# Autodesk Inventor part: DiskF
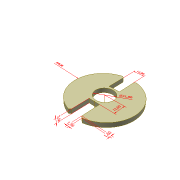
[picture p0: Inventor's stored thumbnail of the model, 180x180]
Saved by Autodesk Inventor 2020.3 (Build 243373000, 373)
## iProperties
Created: 2013-08
Part Number: DiskF
Document SubType Name: Modeling
Designer: hunter love
Density: 1 g/cm^3
Mass: 14.7916 g
Surface Area: 77.5573 cm^2
Volume: 14.7916 cm^3
Material: Generico
Appearance: Nylon 6
Author: hunter love
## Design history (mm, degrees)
node "Annotazioni"
  node "Quota radiale 1" dims "d20" = 35 (derived), "d22" = 21 (derived)
  node "Quota diametro 1" dims "d22" = 21 (derived)
  node "Quota lineare 1" dims "d22" = 21 (derived), "d25" = 12 (derived)
  node "Quota lineare 2" dims "d22" = 21 (derived), "d28" = 5 (derived)
  node "Quota lineare 3" dims "d22" = 21 (derived), "d29" = 1.95741 (derived)
  node "Quota lineare 4" dims "d22" = 21 (derived), "d30" = 1.60154 (derived)
  node "Quota lineare 5" dims "d22" = 21 (derived), "d33" = 12.5 (derived)
sketch "Sketch1"
  geometry: L1 (-6, -34.482)-(-6, -12.5); L2 (-6, -12.5)-(6, -12.5); L3 (6, -12.5)-(6, -34.482); L4 (6, 34.482)-(6, 12.5); L5 (6, 12.5)-(-6, 12.5); L6 (-6, 12.5)-(-6, 34.482); L7 (0, 0)-(30.757, 0) reference; L8 (0, 0)-(0, 25.868) reference; A1 r 35 centre (0, 0) between (-6, 34.482) and (-6, -34.482); A2 r 35 centre (0, 0) between (6, -34.482) and (6, 34.482)
  constraints: 16 end point, 4 point on circle, 2 centre point, 1 horizontal, 1 perpendicular, 1 vertical
  dimensions: "d7" = 6 distance between parallel lines of L4 L8; "d8" = 6 distance between parallel lines of L6 L8; "d9" = 6 distance between parallel lines of L3 L8; "d10" = 6 distance between parallel lines of L8 L1; "d12" = 0 distance of A1.centre L7.start; "d14" = 12.5 distance between parallel lines of L5 L7; "d15" = 12.5 distance between parallel lines of L2 L7
extrude "Extrusion1" new body sketch "Sketch1" distance "d0" = 5; taper "d1" = 0 deg
sketch "Sketch2"
  geometry: C1 r 10.5 at (0, 0)
  constraints: 1 centre point
  dimensions: "d2" = 21 diameter of C1
extrude "Extrusion2" cut sketch "Sketch2" distance "d3" = 10; taper "d4" = 0 deg
chamfer "Chamfer1" distance "d16" = 2; stored, may be unused: second distance "d17" = 2, angle "d18" = 45 deg
node "Asse di lavoro2"
  node "Asse di lavoro1"
node "Solido1"
node "Corpi solidi"
node "Corpi di superficie"
other parameters: "d11" = 35, "d19" = 30.87489 (derived), "d21" = 26.32024 (derived), "d23" = 5.50839 (derived), "d24" = 2.94173 (derived), "d26" = 0 (derived), "d31" = 1.47483 (derived), "d32" = 2.59949 (derived)
